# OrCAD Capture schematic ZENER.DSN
size A
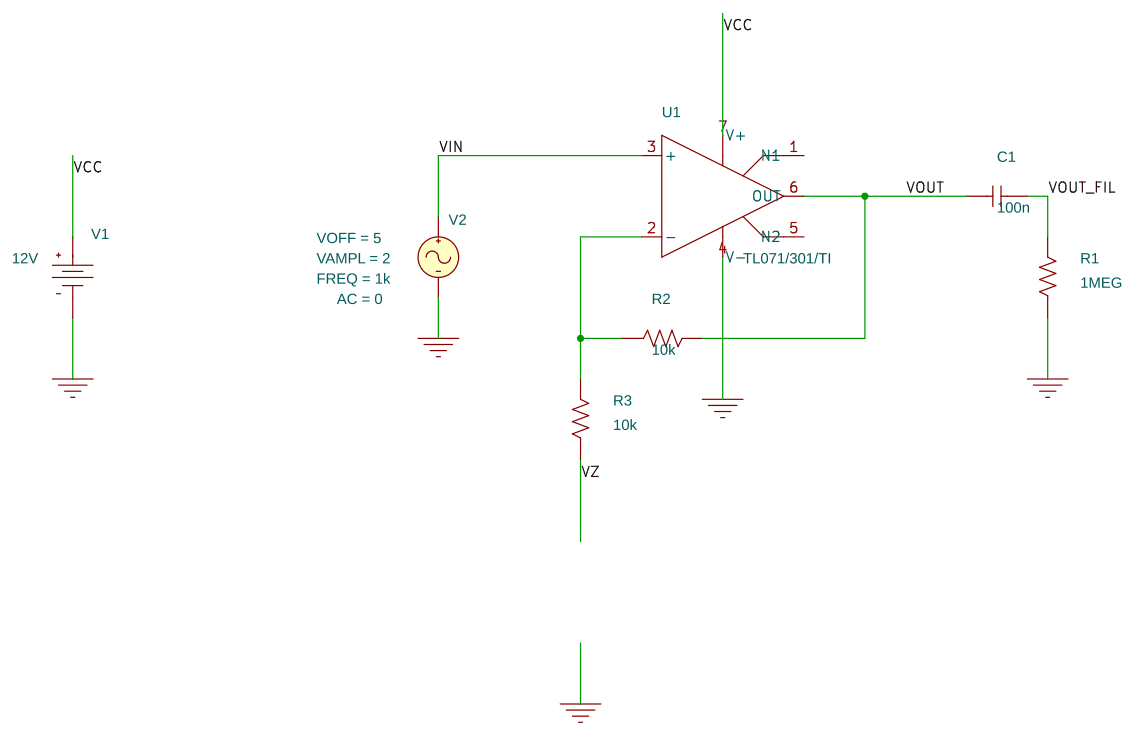
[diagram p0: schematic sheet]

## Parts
C1  100n  [cap196]
R1  1MEG  [AXRC05]
R2  10k  [AXRC05]
R3  10k  [AXRC05]
U1  TL071/301/TI  [DIP1008W300L450]
V1  VDC
V2  VSIN

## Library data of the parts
C1 = C
R1-R3 = R
U1 = TL071_301_TI
V1 = VDC: DC: 12V
V2 = VSIN: AC: 0; AppProp: Sine$Voltage$0$-1; DC: 0; FREQ: 1k; VAMPL: 2; VOFF: 5

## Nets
VCC: U1.7(V+) V1.0(+)
VIN: U1.3(+) V2.1(+)
0: R1.1 U1.4(V-) V1.1(-) V2.2(-)
VOUT: C1.1 R2.2 U1.6(OUT)
VOUT_FIL: C1.2 R1.2
VZ: R3.1
N00470: R2.1 R3.2 U1.2(-)

Not connected (* = marked no-connect by the designer): U1 1(N1) 5(N2)
